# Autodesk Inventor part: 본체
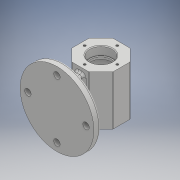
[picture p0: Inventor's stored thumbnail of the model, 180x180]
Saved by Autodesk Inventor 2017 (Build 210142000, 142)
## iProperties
Part Number: 본체
Material: 일반
Document SubType Name: Modeling
Designer: 00-00
Density: 1 g/cm^3
Appearance: 기본값
Author: 00-00
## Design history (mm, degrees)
sketch "스케치1"
  geometry: C1 r 52 at (0, 0); 1 further point
  constraints: 1 centre point, 1 coincident
  dimensions: "d0" = 104 diameter of C1
extrude "돌출1" new body sketch "스케치1" distance "d3" = 10; taper "d4" = 0 deg
sketch "스케치2" dims "d5" = 58
  geometry: L1 (-29, 74.012)-(-12.012, 91); L2 (-12.012, 91)-(12.012, 91); L3 (12.012, 91)-(29, 74.012); L4 (29, 74.012)-(29, 49.988); L5 (29, 49.988)-(12.012, 33); L6 (12.012, 33)-(-12.012, 33); L7 (-12.012, 33)-(-29, 49.988); L8 (-29, 49.988)-(-29, 74.012); L9 (-52, 0)-(52, 0) reference; 5 further points
  constraints: 16 end point, 2 midpoint, 1 coincident, 1 horizontal alignment, 1 vertical, 1 vertical alignment, 19 other
  dimensions: "d6" = 62 distance from line of L9 point (0, 62)
extrude "돌출2" join sketch "스케치2" stored distance "d7" = 70; taper "d8" = 0 deg
sketch "스케치3"
  geometry: L1 (62, 52.005)-(62, -52.005); L2 (91, 35)-(74.012, 35) reference; L3 (78, 35)-(78, 23); L4 (78, 23)-(76, 23); L5 (76, 23)-(76, 20); L6 (76, 20)-(84, 20); L7 (84, 20)-(84, -20); L8 (84, -20)-(76, -20); L9 (76, -20)-(76, -23); L10 (76, -23)-(78, -23); L11 (78, -23)-(78, -35); L12 (74.012, -35)-(91, -35) reference; L13 (78, 35)-(62, 35); L14 (74.012, 35)-(49.988, 35) reference; L15 (78, -35)-(62, -35); L16 (49.988, -35)-(74.012, -35) reference; L17 (62, 35)-(62, -35); 3 further points
  constraints: 26 end point, 6 perpendicular, 6 point on line, 4 midpoint, 2 vertical, 1 collinear, 1 horizontal alignment
  dimensions: "d9" = 62 horizontal distance of point (0, 0) L1.end; "d10" = 44 diameter of L7 L1; "d11" = 32 diameter of L3 L1; "d12" = 28 diameter of L5 L1; "d13" = 40 distance of L6.end L7.end; "d14" = 12 distance of L3.start L3.end; "d15" = 12 distance of L10.end L11.end; "d16" = 3 distance of L8.end L9.end
revolve "회전1" sketch "스케치3" stored, may be unused: angle "d17" = 90 deg
sketch "스케치4"
  geometry: L1 (-5, -28)-(5, -28); L2 (5, -28)-(5, 28); L3 (5, 28)-(-5, 28); L4 (-5, 28)-(-5, -28); 3 further points
  constraints: 8 end point, 2 midpoint, 2 perpendicular, 1 horizontal, 1 horizontal alignment, 1 vertical alignment
  dimensions: "d18" = 10 distance of L1.start L1.end; "d19" = 56 distance of L1.end L2.end; "d20" = 10 distance of L2.end L3.end; "d21" = 56 distance of L3.end L1.start (derived)
extrude "돌출3" join sketch "스케치4" stored distance "d22" = 70; taper "d23" = 0 deg
fillet "모깎기1" dims "d24" = 3
fillet "모깎기2" dims "d25" = 3
sketch "스케치5"
  geometry: L1 (29, 74.012)-(12.012, 91) reference; L2 (12.012, 91)-(-12.012, 91) reference; L3 (-12.012, 91)-(-29, 74.012) reference; L4 (-29, 74.012)-(-29, 49.988) reference; L5 (-29, 49.988)-(-12.012, 33) reference; L6 (-12.012, 33)-(12.012, 33) reference; L7 (12.012, 33)-(29, 49.988) reference; L8 (29, 49.988)-(29, 74.012) reference; C1 r 16 at (0, 62) reference; 5 further points
  constraints: 1 vertical alignment, 5 other
  dimensions: "d28" = 360 deg dimension on C1.centre point (0, 85) (derived); "d30" = 23 distance of C1.centre point (0, 85)
hole "구멍1" sketch "스케치5" at (0, 85), (-23, 62), (0, 39), (23, 62) diameter "d31" = 3.242; stored, may be unused: countersink angle "d35" = 90 deg, drill point angle "d37" = 118 deg; dims "d32" = 8, "d33" = 4, "d34" = 2, "d36" = 10
sketch "스케치6"
  geometry: L1 (0, 0)-(-24.024, 0) reference; L2 (-41.012, 70)-(-41.012, 0) reference; C1 r 10 at (-12.012, 35); 1 further point
  constraints: 1 centre point
  dimensions: "d38" = 20 diameter of C1; "d39" = 35 distance from line of L1 C1.centre; "d40" = 29 distance from line of L2 C1.centre
extrude "돌출4" join sketch "스케치6" distance "d41" = 5; taper "d42" = 0 deg
sketch "스케치7"
  geometry: C1 r 10 at (0, 0) reference; 1 further point
hole "구멍2" sketch "스케치7" at (0, 0) diameter "d43" = 10.106; stored, may be unused: countersink angle "d47" = 90 deg, drill point angle "d49" = 118 deg; dims "d44" = 50, "d45" = 16, "d46" = 2, "d48" = 50
sketch "스케치8"
  geometry: 5 further points
  constraints: 2 horizontal alignment, 5 other
  dimensions: "d52" = 360 deg dimension on point (0, 0) point (41, 0) (derived); "d54" = 41 distance of point (0, 0) point (41, 0)
hole "구멍3" sketch "스케치8" at (41, 0), (0, 41), (-41, 0), (0, -41) diameter "d55" = 9; stored, may be unused: countersink angle "d59" = 90 deg, drill point angle "d61" = 118 deg; dims "d56" = 50, "d57" = 16, "d58" = 2, "d60" = 50
sketch "스케치9"
  geometry: L1 (24.024, 70)-(41.012, 70) reference; 2 further points
  constraints: 1 other
  dimensions: "d62" = 35 distance from line of L1 point (11.776, 35)
feature "엠보싱1" sketch "스케치9" dims "d63" = 0.5, "d64" = 0
chamfer "모따기1" distance "d65" = 1; stored, may be unused: second distance "d66" = 2, angle "d67" = 45 deg
chamfer "모따기2" distance "d68" = 1; stored, may be unused: second distance "d69" = 2, angle "d70" = 45 deg
fillet "모깎기3" dims "d71" = 0.3
fillet "모깎기4" dims "d72" = 3
fillet "모깎기5" dims "d73" = 3
fillet "모깎기6" dims "d74" = 1
fillet "모깎기7" dims "d75" = 1
node "솔리드1"
mirror "미러1"
node "투영된 루프1"
node "투영된 루프2"
